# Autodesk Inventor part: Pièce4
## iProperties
Shininess: 64.0
Length Units: 11269
Angle Units: 11279
Time Units: 11290
Mass Units: 11283
Length Display Precision: 3
Angle Display Precision: 2
Compacted: True
Part Number: Pièce4
Document SubType Name: Modeling
Created: 2004-06
Material: Par défaut
Designer: administrateur
Density: 0.0
Volumn: 0.0
Area: 0.0
PropertySet Name: Model Information
Control State: 0
Master: False
Checked Out: False
Author: administrateur
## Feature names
1. Balayage1
2. Extrusion1
3. Extrusion2
4. Balayage2
5. Extrusion4
